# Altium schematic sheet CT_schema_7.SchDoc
size 368 x 245 mm
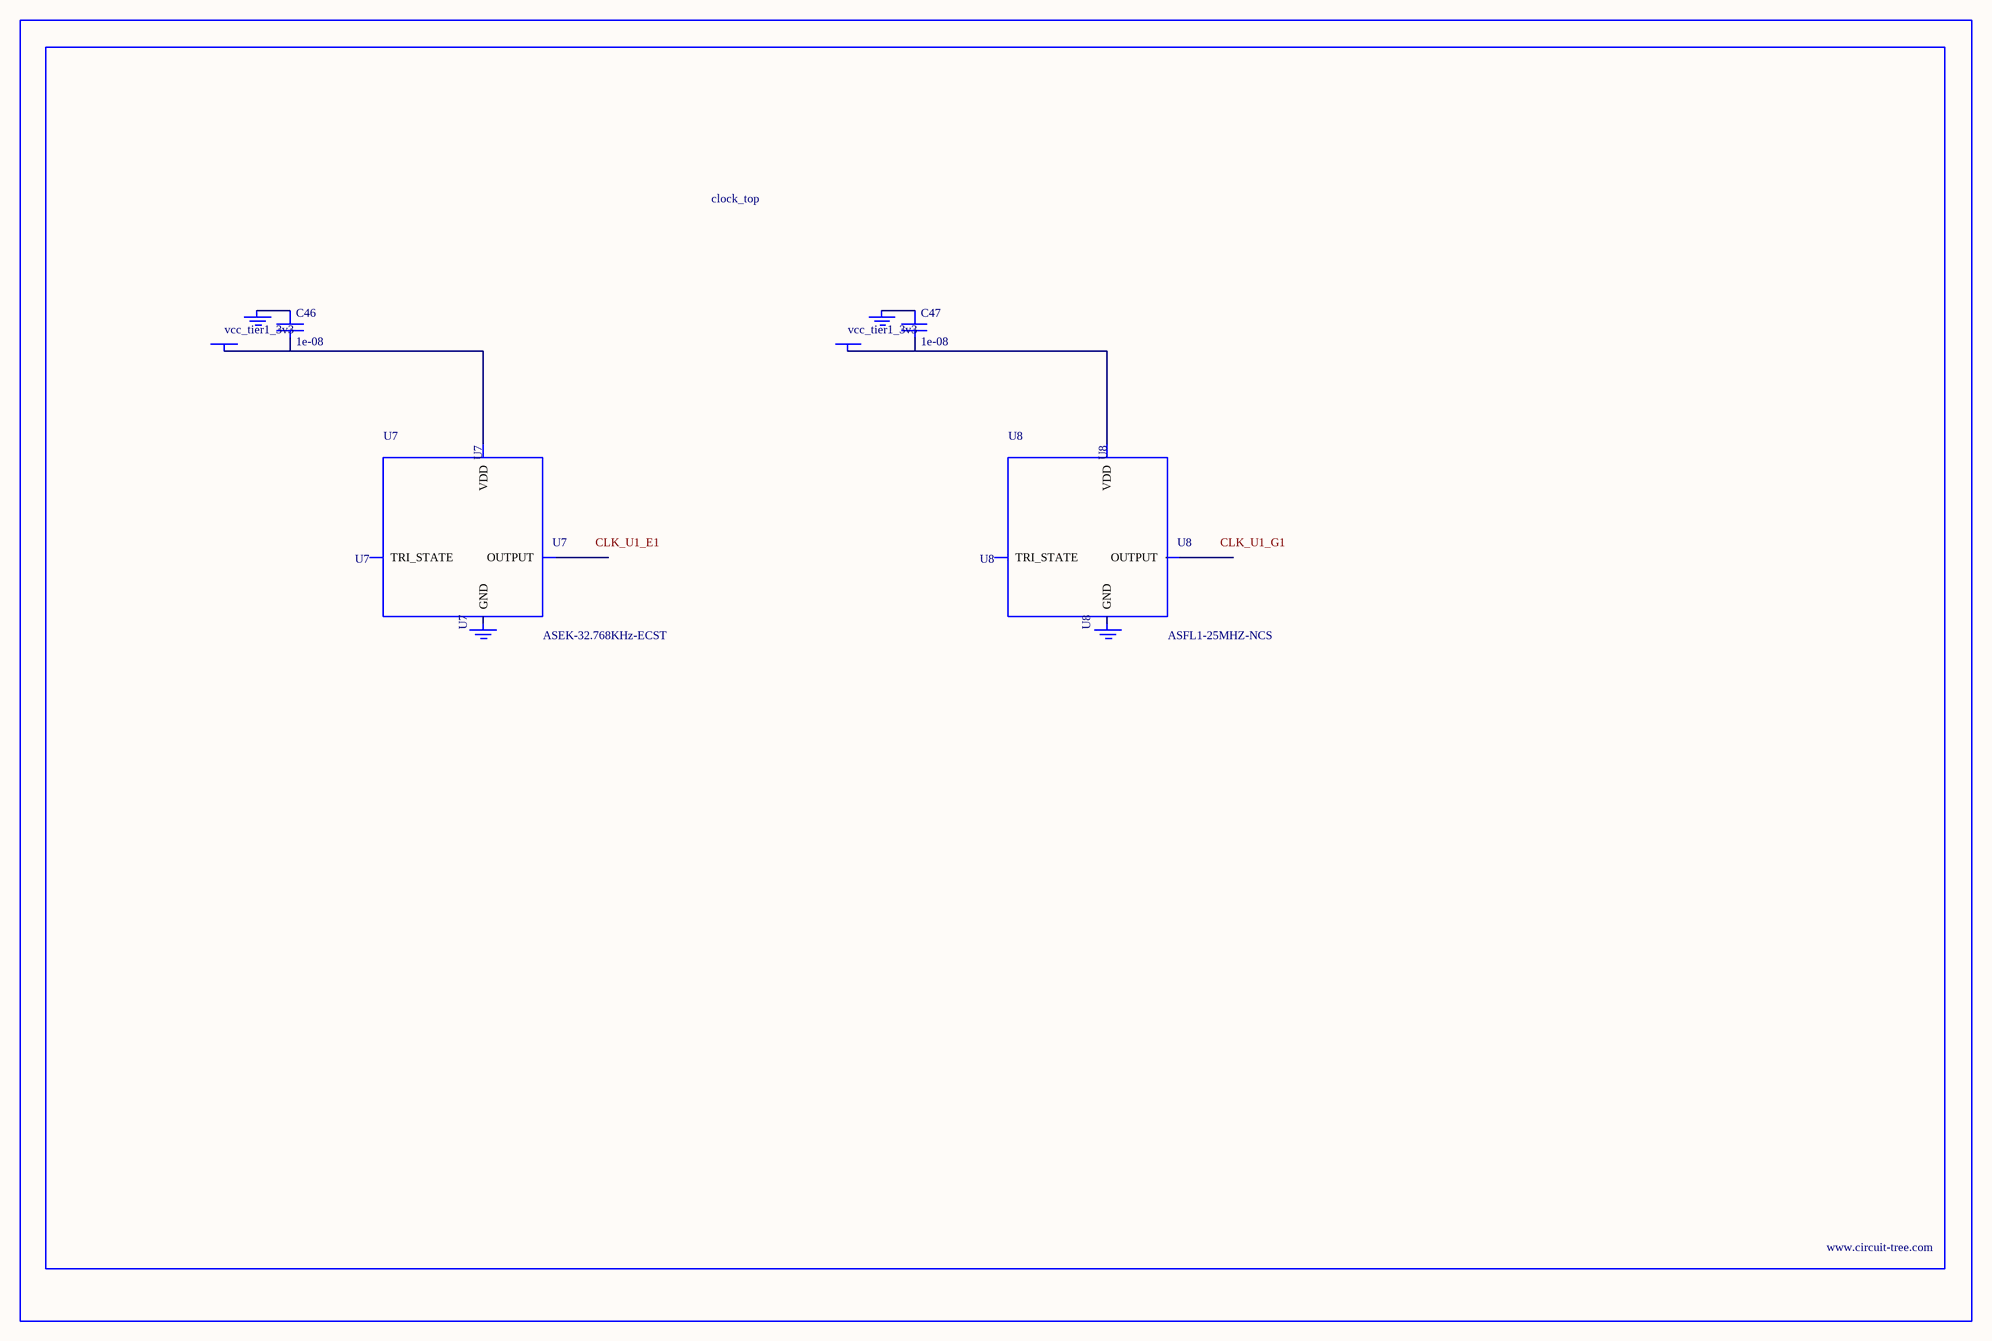
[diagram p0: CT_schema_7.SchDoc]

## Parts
BORDER6  (no value)
C46  1e-08  [C0402]
C47  1e-08  [C0402]
GND_INSTANCE_6_0  (no value)
GND_INSTANCE_6_1  (no value)
GND_INSTANCE_6_2  (no value)
GND_INSTANCE_6_3  (no value)
POWER_INSTANCE_6_0  vcc_tier1_3v3
POWER_INSTANCE_6_1  vcc_tier1_3v3
U7  ASEK-32.768KHz-ECST  [ASEK]
U8  ASFL1-25MHZ-NCS  [ASFL1]

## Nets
NetC46_1: C46.1 GND_INSTANCE_6_0.0(GND)
NetC46_2: C46.2 POWER_INSTANCE_6_0.0(PWR) U7.4(VDD)
NetC47_1: C47.1 GND_INSTANCE_6_2.0(GND)
NetC47_2: C47.2 POWER_INSTANCE_6_1.0(PWR) U8.4(VDD)

Not connected (* = marked no-connect by the designer): GND_INSTANCE_6_1 0(GND); GND_INSTANCE_6_3 0(GND); U7 1(TRI_STATE) 2(GND) 3(OUTPUT); U8 1(TRI_STATE) 2(GND) 3(OUTPUT)

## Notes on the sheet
- Labels drawn without touching a wire or pin: CLK_U1_E1, CLK_U1_G1

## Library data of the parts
BORDER6 = BORDER_PAGE6
C46 C47 = C0402C103K3RAC
GND_INSTANCE_6_0-GND_INSTANCE_6_3 = GND
POWER_INSTANCE_6_0 POWER_INSTANCE_6_1 = PWR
